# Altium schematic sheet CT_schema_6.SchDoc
size 365 x 245 mm
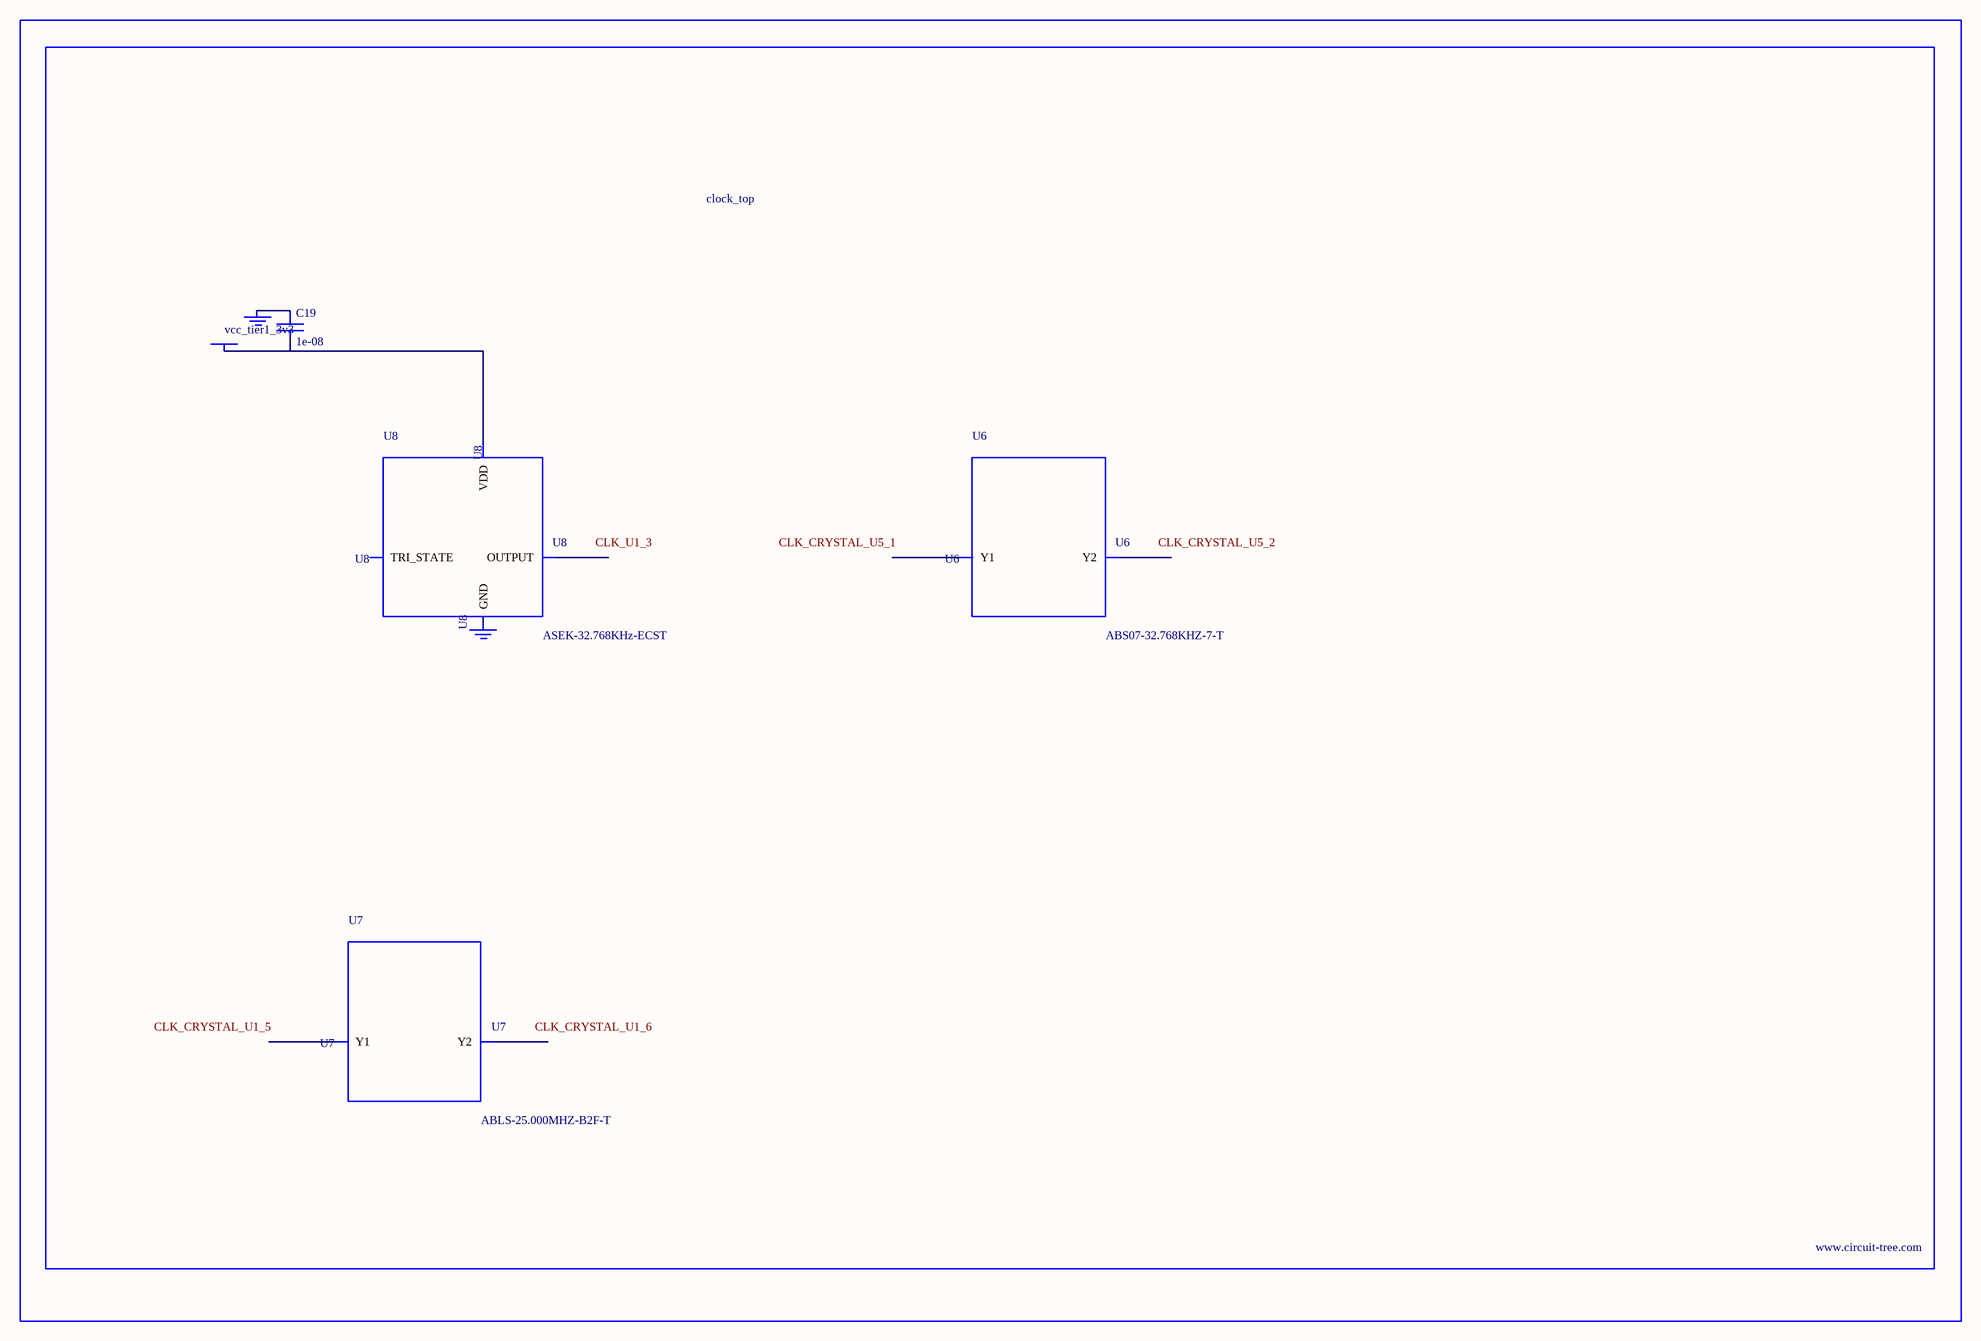
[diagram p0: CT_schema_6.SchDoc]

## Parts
BORDER5  (no value)
C19  1e-08  [C0402]
GND_INSTANCE_5_0  (no value)
GND_INSTANCE_5_1  (no value)
POWER_INSTANCE_5_0  vcc_tier1_3v3
U6  ABS07-32.768KHZ-7-T  [ABS07-32.768KHZ-7-T]
U7  ABLS-25.000MHZ-B2F-T  [ABLS-25.000MHZ-B2F-T]
U8  ASEK-32.768KHz-ECST  [ASEK]

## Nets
NetC19_1: C19.1 GND_INSTANCE_5_0.0(GND)
NetC19_2: C19.2 POWER_INSTANCE_5_0.0(PWR) U8.4(VDD)

Not connected (* = marked no-connect by the designer): GND_INSTANCE_5_1 0(GND); U6 1(Y1) 2(Y2); U7 1(Y1) 2(Y2); U8 1(TRI_STATE) 2(GND) 3(OUTPUT)

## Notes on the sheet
- Labels drawn without touching a wire or pin: CLK_CRYSTAL_U1_5, CLK_CRYSTAL_U1_6, CLK_CRYSTAL_U5_1, CLK_CRYSTAL_U5_2, CLK_U1_3

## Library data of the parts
BORDER5 = BORDER_PAGE5
C19 = C0402C103K3RAC
GND_INSTANCE_5_0 GND_INSTANCE_5_1 = GND
POWER_INSTANCE_5_0 = PWR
